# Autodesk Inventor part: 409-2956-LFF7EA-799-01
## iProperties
Created: 2010-11
Part Number: 409-2956-LFF7EA-799-01
Material: 3/4" OD TUBE - SS
Document SubType Name: Modeling
Designer: S. Boerckel
Engineer: Steve Boerckel
Mass: 55.5632 g
Surface Area: 85.1076 cm^2
Volume: 6.87664 cm^3
Density: 8.08 g/cm^3
Description: DRAIN TUBING
User Status: CUT
Length: 3.000 in
Author: S. Boerckel
Revision Number: 0
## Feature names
1. Extrusion1
